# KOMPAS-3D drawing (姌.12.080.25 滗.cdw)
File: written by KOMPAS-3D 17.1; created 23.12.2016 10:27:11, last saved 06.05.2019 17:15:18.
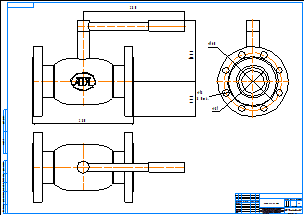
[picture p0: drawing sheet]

Sheet 1: A1, landscape

Title block, sheet 1: name: КШ.12.080.25 фф; material: Внимание! Данный продукт является объектом авторского права ООО «Торговый Дом АДЛ». / Запрещается изменение, копирование, распространение / (в том числе путем копирования на другие сайты и ресурсы в Интернете) / или любое иное использование информации и объектов без предварительного / согласия правообладателя (ООО «Торговый Дом АДЛ»).; sheets: 1; organisation: ООО "Торговый дом АДЛ"; sheet format: A1; stored path: C:\Users\tra\Desktop\2д чертежи\Шаровые краны БИВАЛ\КШ_Бивал_серия_11_12\KOMPAS_2D\КШ.12.080.25 фф.cdw

Views: Вид 1, Проекционный вид 2, Проекционный вид 3
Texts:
  Klimkovich
  ADL
Dimensions and other numbers on the sheet: 280; 168,8; 97,5; 160; 81; 18; 8 Отв.; 1:1; 1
